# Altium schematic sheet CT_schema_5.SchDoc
size 293 x 258 mm
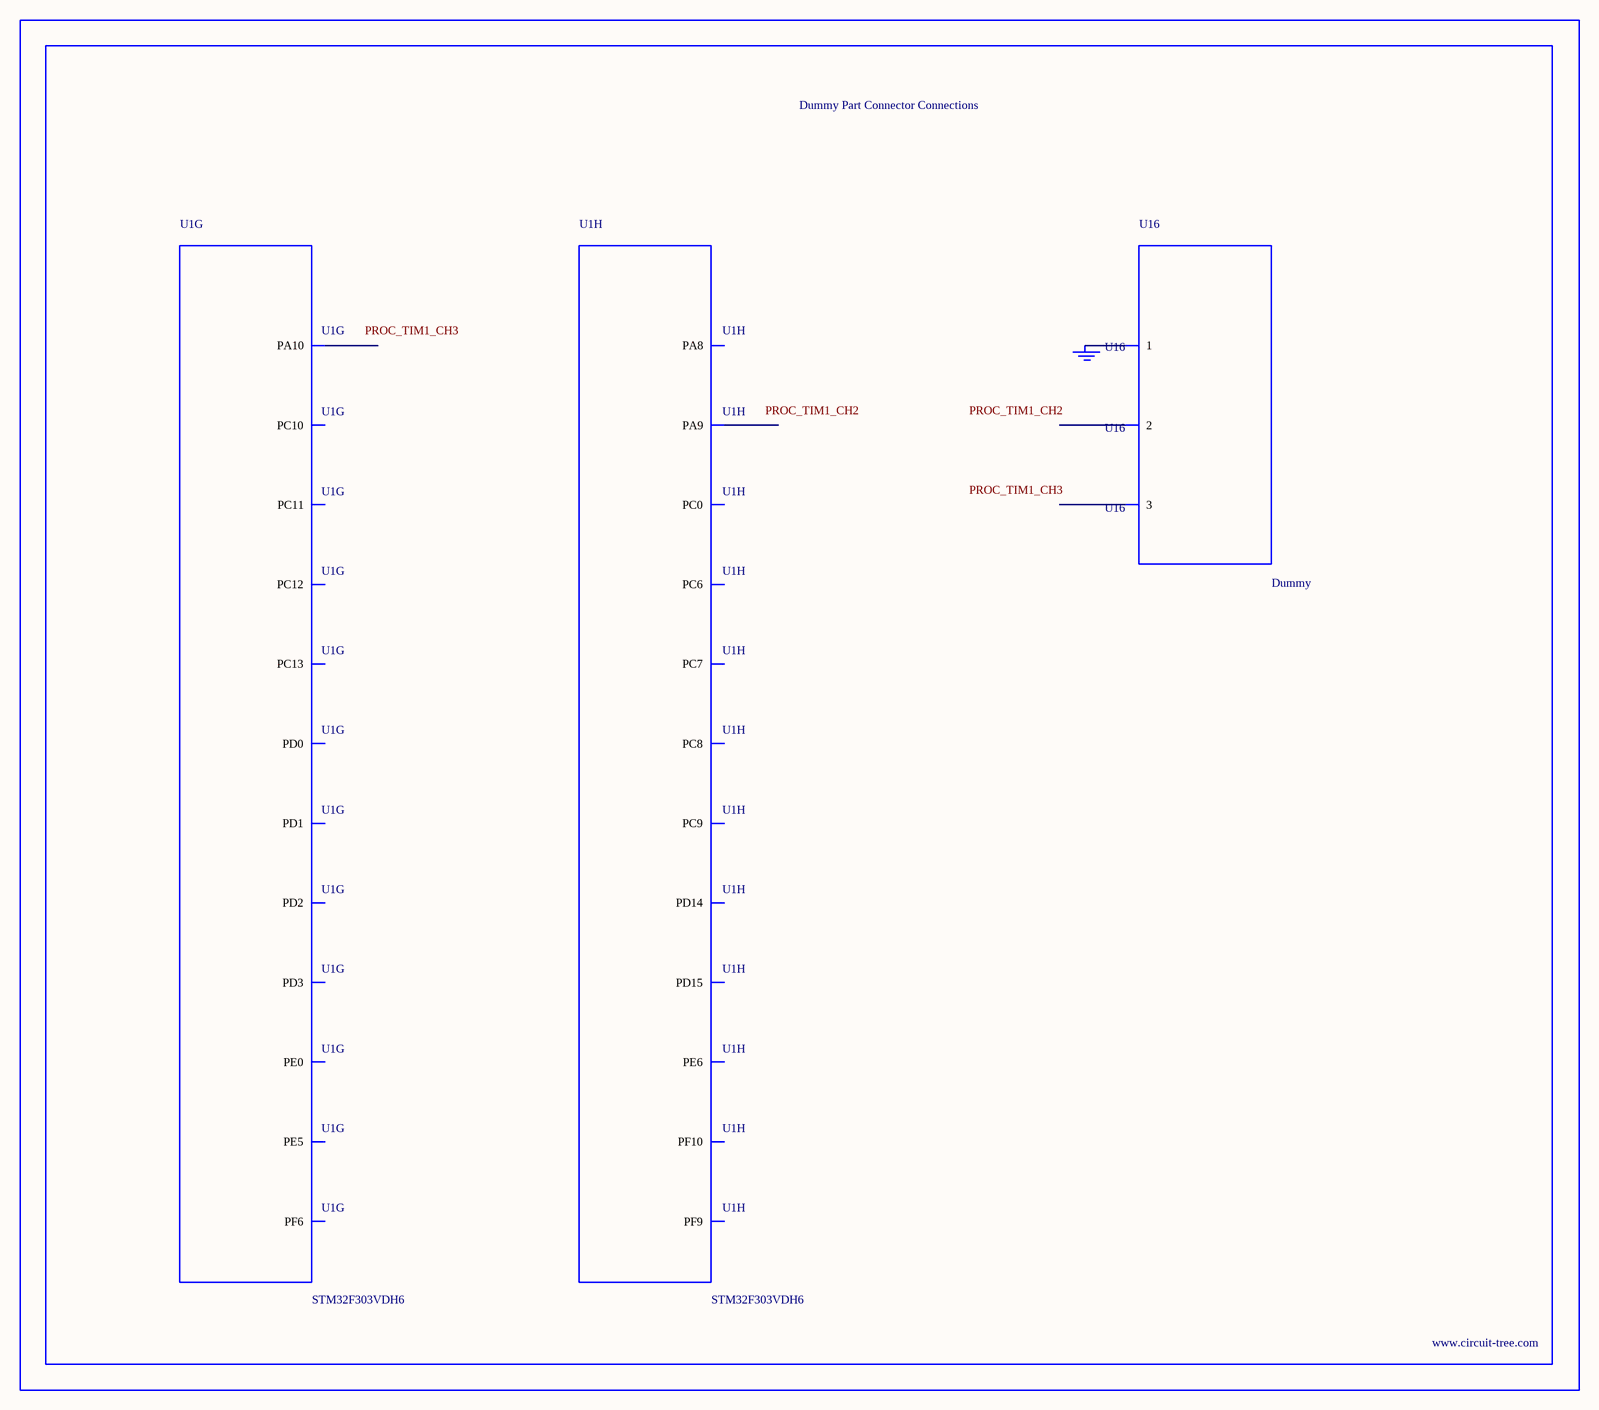
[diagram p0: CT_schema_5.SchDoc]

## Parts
BORDER4  (no value)
GND_INSTANCE_4_0  (no value)
U1  STM32F303VDH6  [UFBGA100]  (parts G,H of 8)
U16  Dummy  [DUMMY_PACKAGE_122]

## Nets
NetGND_INSTANCE_4_0_0: GND_INSTANCE_4_0.0(GND) U16.1

Not connected (* = marked no-connect by the designer): U1 B8(PD3) B9(PD1) B10(PC12) B11(PC10) C1(PC13) C2(PE5) C3(PE0) C8(PD2) C9(PD0) C10(PC11) C11(PF6) C12(PA10) D2(PE6) D10(PA9) D11(PA8) D12(PC9) E10(PC8) E11(PC7) E12(PC6) F2(PF9) G2(PF10) H1(PC0) H10(PD15) H11(PD14); U16 2 3

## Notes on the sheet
- Labels drawn without touching a wire or pin: PROC_TIM1_CH2, PROC_TIM1_CH3

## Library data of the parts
BORDER4 = BORDER_PAGE4
GND_INSTANCE_4_0 = GND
